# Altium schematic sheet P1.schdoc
size 297 x 209 mm; Symbol: Drawing-Symbol_A4; @Project Name: Reflectle; @Page Count: 1; @Update Date: 2026-10-31; @Create Date: 2026-10-31; @Schematic Name: Schematic2; @Page No: 1; @Page Name: P1; Company: EasyEDA.com; Version: V1.0; Page Size: A4; Device: Drawing-Symbol_A4; @Create Time: 22:20:12; @Update Time: 22:20:12; Border: 1; Width: 1170; Height: 825; Region Start: 1; X Region Count: 6; Y Region Count: 4; Blade Width: 10; Title Block Position: 3; @Board Name: PCB2
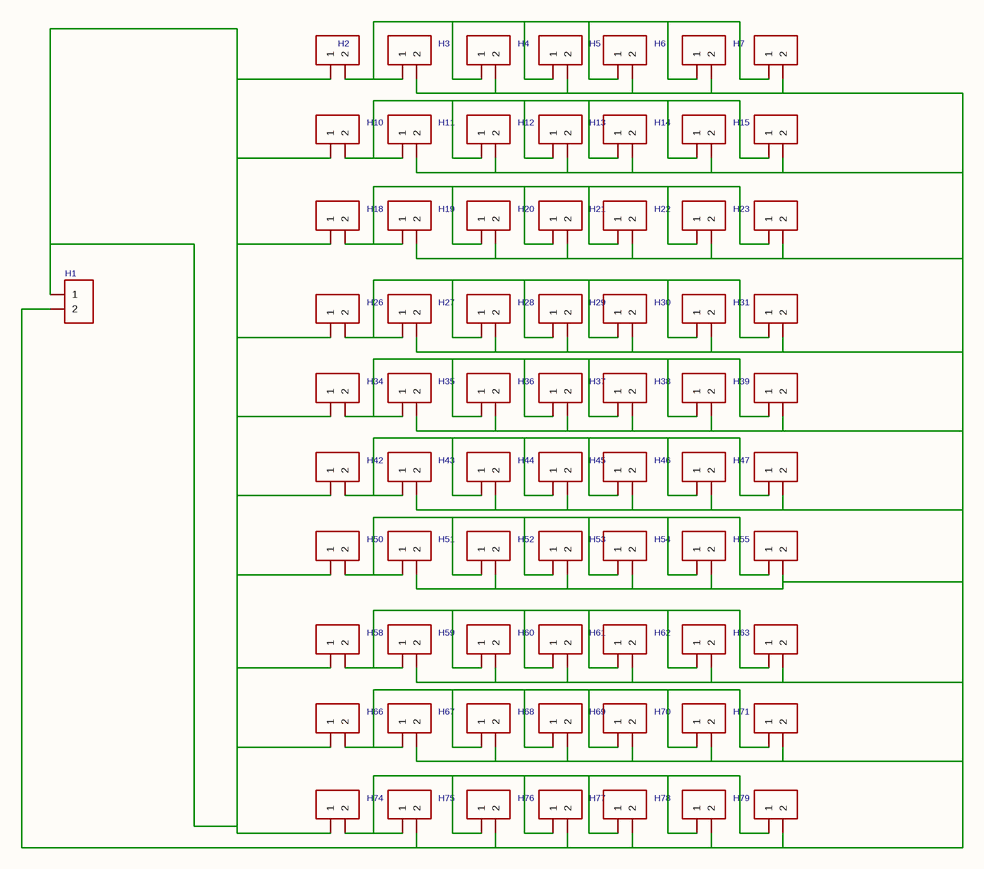
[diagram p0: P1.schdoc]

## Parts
H1  (no value)  [HDR-TH_2P-P2.54-V-F]
H2  (no value)  [HDR-TH_2P-P2.54-V-F]
H3  (no value)  [HDR-TH_2P-P2.54-V-F]
H4  (no value)  [HDR-TH_2P-P2.54-V-F]
H5  (no value)  [HDR-TH_2P-P2.54-V-F]
H6  (no value)  [HDR-TH_2P-P2.54-V-F]
H7  (no value)  [HDR-TH_2P-P2.54-V-F]
H8  (no value)  [HDR-TH_2P-P2.54-V-F]
H10  (no value)  [HDR-TH_2P-P2.54-V-F]
H11  (no value)  [HDR-TH_2P-P2.54-V-F]
H12  (no value)  [HDR-TH_2P-P2.54-V-F]
H13  (no value)  [HDR-TH_2P-P2.54-V-F]
H14  (no value)  [HDR-TH_2P-P2.54-V-F]
H15  (no value)  [HDR-TH_2P-P2.54-V-F]
H16  (no value)  [HDR-TH_2P-P2.54-V-F]
H18  (no value)  [HDR-TH_2P-P2.54-V-F]
H19  (no value)  [HDR-TH_2P-P2.54-V-F]
H20  (no value)  [HDR-TH_2P-P2.54-V-F]
H21  (no value)  [HDR-TH_2P-P2.54-V-F]
H22  (no value)  [HDR-TH_2P-P2.54-V-F]
H23  (no value)  [HDR-TH_2P-P2.54-V-F]
H24  (no value)  [HDR-TH_2P-P2.54-V-F]
H26  (no value)  [HDR-TH_2P-P2.54-V-F]
H27  (no value)  [HDR-TH_2P-P2.54-V-F]
H28  (no value)  [HDR-TH_2P-P2.54-V-F]
H29  (no value)  [HDR-TH_2P-P2.54-V-F]
H30  (no value)  [HDR-TH_2P-P2.54-V-F]
H31  (no value)  [HDR-TH_2P-P2.54-V-F]
H32  (no value)  [HDR-TH_2P-P2.54-V-F]
H34  (no value)  [HDR-TH_2P-P2.54-V-F]
H35  (no value)  [HDR-TH_2P-P2.54-V-F]
H36  (no value)  [HDR-TH_2P-P2.54-V-F]
H37  (no value)  [HDR-TH_2P-P2.54-V-F]
H38  (no value)  [HDR-TH_2P-P2.54-V-F]
H39  (no value)  [HDR-TH_2P-P2.54-V-F]
H40  (no value)  [HDR-TH_2P-P2.54-V-F]
H42  (no value)  [HDR-TH_2P-P2.54-V-F]
H43  (no value)  [HDR-TH_2P-P2.54-V-F]
H44  (no value)  [HDR-TH_2P-P2.54-V-F]
H45  (no value)  [HDR-TH_2P-P2.54-V-F]
H46  (no value)  [HDR-TH_2P-P2.54-V-F]
H47  (no value)  [HDR-TH_2P-P2.54-V-F]
H48  (no value)  [HDR-TH_2P-P2.54-V-F]
H50  (no value)  [HDR-TH_2P-P2.54-V-F]
H51  (no value)  [HDR-TH_2P-P2.54-V-F]
H52  (no value)  [HDR-TH_2P-P2.54-V-F]
H53  (no value)  [HDR-TH_2P-P2.54-V-F]
H54  (no value)  [HDR-TH_2P-P2.54-V-F]
H55  (no value)  [HDR-TH_2P-P2.54-V-F]
H56  (no value)  [HDR-TH_2P-P2.54-V-F]
H58  (no value)  [HDR-TH_2P-P2.54-V-F]
H59  (no value)  [HDR-TH_2P-P2.54-V-F]
H60  (no value)  [HDR-TH_2P-P2.54-V-F]
H61  (no value)  [HDR-TH_2P-P2.54-V-F]
H62  (no value)  [HDR-TH_2P-P2.54-V-F]
H63  (no value)  [HDR-TH_2P-P2.54-V-F]
H64  (no value)  [HDR-TH_2P-P2.54-V-F]
H66  (no value)  [HDR-TH_2P-P2.54-V-F]
H67  (no value)  [HDR-TH_2P-P2.54-V-F]
H68  (no value)  [HDR-TH_2P-P2.54-V-F]
H69  (no value)  [HDR-TH_2P-P2.54-V-F]
H70  (no value)  [HDR-TH_2P-P2.54-V-F]
H71  (no value)  [HDR-TH_2P-P2.54-V-F]
H72  (no value)  [HDR-TH_2P-P2.54-V-F]
H74  (no value)  [HDR-TH_2P-P2.54-V-F]
H75  (no value)  [HDR-TH_2P-P2.54-V-F]
H76  (no value)  [HDR-TH_2P-P2.54-V-F]
H77  (no value)  [HDR-TH_2P-P2.54-V-F]
H78  (no value)  [HDR-TH_2P-P2.54-V-F]
H79  (no value)  [HDR-TH_2P-P2.54-V-F]
H80  (no value)  [HDR-TH_2P-P2.54-V-F]

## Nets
NetH1_1: H1.1 H2.1 H10.1 H18.1 H26.1 H34.1 H42.1 H50.1 H58.1 H66.1 H74.1
NetH1_2: H1.2 H3.2 H4.2 H5.2 H6.2 H7.2 H8.2 H11.2 H12.2 H13.2 H14.2 H15.2 H16.2 H19.2 H20.2 H21.2 H22.2 H23.2 H24.2 H27.2 H28.2 H29.2 H30.2 H31.2 H32.2 H35.2 H36.2 H37.2 H38.2 H39.2 H40.2 H43.2 H44.2 H45.2 H46.2 H47.2 H48.2 H51.2 H52.2 H53.2 H54.2 H55.2 H56.2 H59.2 H60.2 H61.2 H62.2 H63.2 H64.2 H67.2 H68.2 H69.2 H70.2 H71.2 H72.2 H75.2 H76.2 H77.2 H78.2 H79.2 H80.2
NetH2_2: H2.2 H3.1 H4.1 H5.1 H6.1 H7.1 H8.1
NetH10_2: H10.2 H11.1 H12.1 H13.1 H14.1 H15.1 H16.1
NetH18_2: H18.2 H19.1 H20.1 H21.1 H22.1 H23.1 H24.1
NetH26_2: H26.2 H27.1 H28.1 H29.1 H30.1 H31.1 H32.1
NetH34_2: H34.2 H35.1 H36.1 H37.1 H38.1 H39.1 H40.1
NetH42_2: H42.2 H43.1 H44.1 H45.1 H46.1 H47.1 H48.1
NetH50_2: H50.2 H51.1 H52.1 H53.1 H54.1 H55.1 H56.1
NetH58_2: H58.2 H59.1 H60.1 H61.1 H62.1 H63.1 H64.1
NetH66_2: H66.2 H67.1 H68.1 H69.1 H70.1 H71.1 H72.1
NetH74_2: H74.2 H75.1 H76.1 H77.1 H78.1 H79.1 H80.1

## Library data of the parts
H1-H8 H10-H16 H18-H24 H26-H32 H34-H40 H42-H48 H50-H56 H58-H64 H66-H72 H74-H80 = HDR-F_2.54_1x2P: Manufacturer: BOOMELE(博穆精密); Manufacturer Part: 2.54-1*2P母; Symbol: Header-Female-2.54_1x2; ConvertToPcb: yes; ModelId: 925d5dffa823422895d76d9dc6f5e8cd0819f05c4eef4c71ace90d822a990e87; ModelName: HDR-TH_2P-P2.54-F-LI-1X2P; ModelTransform: 215.7476,98.425,0,0,0,0,0,0,-129.921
